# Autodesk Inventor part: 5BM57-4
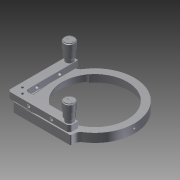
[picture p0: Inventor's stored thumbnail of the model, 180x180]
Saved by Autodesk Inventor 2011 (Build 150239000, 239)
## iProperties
Created: 2011-06
Part Number: 5BM57-4
Document SubType Name: Modeling
Designer: vadybininkas6
Density: 1 g/cm^3
Author: vadybininkas6
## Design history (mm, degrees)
feature "Base1"
body "Solid1"
